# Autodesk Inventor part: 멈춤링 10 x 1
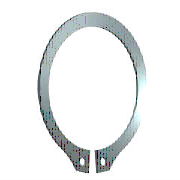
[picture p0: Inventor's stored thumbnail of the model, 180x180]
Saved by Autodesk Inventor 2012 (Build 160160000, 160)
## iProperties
IsCustomPart: 0
Company: 한국ATC센터
Created: 2014-07
Part Number: 멈춤링 10 x 1
Material: Steel, Mild
Description: 리테이닝 링(C형)
Document SubType Name: Modeling
Standard: KS B 1336
Designer: KYOUNG IL JANG
Standards Organization: KS
Language: ko-KR
Size Designation: 10 x 1
Categories: <MemberInstance><Categories><Category DisplayName="샤프트 부품" InternalName="7f7aeb1f-a693-4053-b835-cee3144e0d98" Mnemonic="SHFT"><Category DisplayName="써클립" Inter
Density: 7.86 g/cm^3
Mass: 0.423084 g
Surface Area: 1.9243 cm^2
Volume: 0.0538275 cm^3
Author: KYOUNG IL JANG
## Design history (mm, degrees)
sketch "스케치1"
  geometry: L1 (-6, 0)-(6, 0) reference; L2 (0, 20.189)-(0, -80.536) reference; L3 (-48.09, 0)-(48.09, 0) reference; L4 (-0.3, -9.791)-(-0.3, -12.791); L5 (-0.3, -6.54)-(-0.3, -13.29); L6 (-2.795, 1.6)-(3.672, 1.6); L7 (0.3, -6.54)-(0.3, -13.29); L8 (0.3, -9.791)-(0.3, -12.791); C1 r 0.6 at (-1.2, -11.486); C2 r 0.6 at (1.2, -11.486); A1 r 4.8 centre (0, -5) between (0.3, -9.791) and (-0.3, -9.791); A2 r 6.2 centre (0, -4.6) between (2.988, -10.033) and (-2.988, -10.033); A3 r 7.796 centre (0, -5) between (-1.418, -12.666) and (-0.3, -12.791); A4 r 1.2 centre (-1.2, -11.486) between (-2.383, -11.285) and (-1.418, -12.666); A5 r 1.2 centre (-3.566, -11.084) between (-2.383, -11.285) and (-2.988, -10.033); A6 r 1.2 centre (3.566, -11.084) between (2.988, -10.033) and (2.383, -11.285); A7 r 1.2 centre (1.2, -11.486) between (1.418, -12.666) and (2.383, -11.285); A8 r 7.796 centre (0, -5) between (0.3, -12.791) and (1.418, -12.666)
  constraints: 16 point on circle, 12 end point, 10 centre point, 9 symmetric about line, 5 point on line, 4 tangent, 3 coincident, 2 horizontal, 1 perpendicular, 1 vertical, 5 other
  dimensions: "d0" = 9.6 diameter of A1 (= ND); "d1" = 3 distance of L4.end L4.start (= SRB2); "d6" = 0.3 distance between parallel lines of L2 L5 (= 0.25 x SD5); "d7" = 1.6 distance between parallel lines of L6 L3 (= SRB1); "d8" = 0.4 distance of A1.centre A2.centre (= 0.25 x SRB1); "d9" = 1.2 radius of A4 (= SD5); "d10" = 1.2 radius of A5 (= SD5); "d11" = 0.9 distance from line of L4 A4.centre (= 0.75 x SD5); "d12" = 1.2 diameter of C1 (= SD5); "d13" = 1.2 diameter of C2 (= SD5); "d14" = 5 distance from line of A1.centre L1 (= 0.5 x WD)
extrude "본체" new body sketch "스케치1" distance "d2" = 1 (= SD); taper "d3" = 0 deg
workaxis "Work Axis1"
workplane "Work Plane1"
body "Solid1"
other parameters: "SD" = 1 [user parameter; used in 1 equation term], "SRB1" = 1.6 [user parameter; used in 2 equation terms], "ND" = 9.6 [user parameter; used in 1 equation term], "SRB2" = 3 [user parameter; used in 1 equation term], "SD5" = 1.2 [user parameter; used in 6 equation terms], "d15" = 0, "d16" = 0, "d17" = 0, "d41" = 0, "d42" = 0, "SD3" = 9.3 [user parameter], "WDMAX" = 11 [user parameter]
